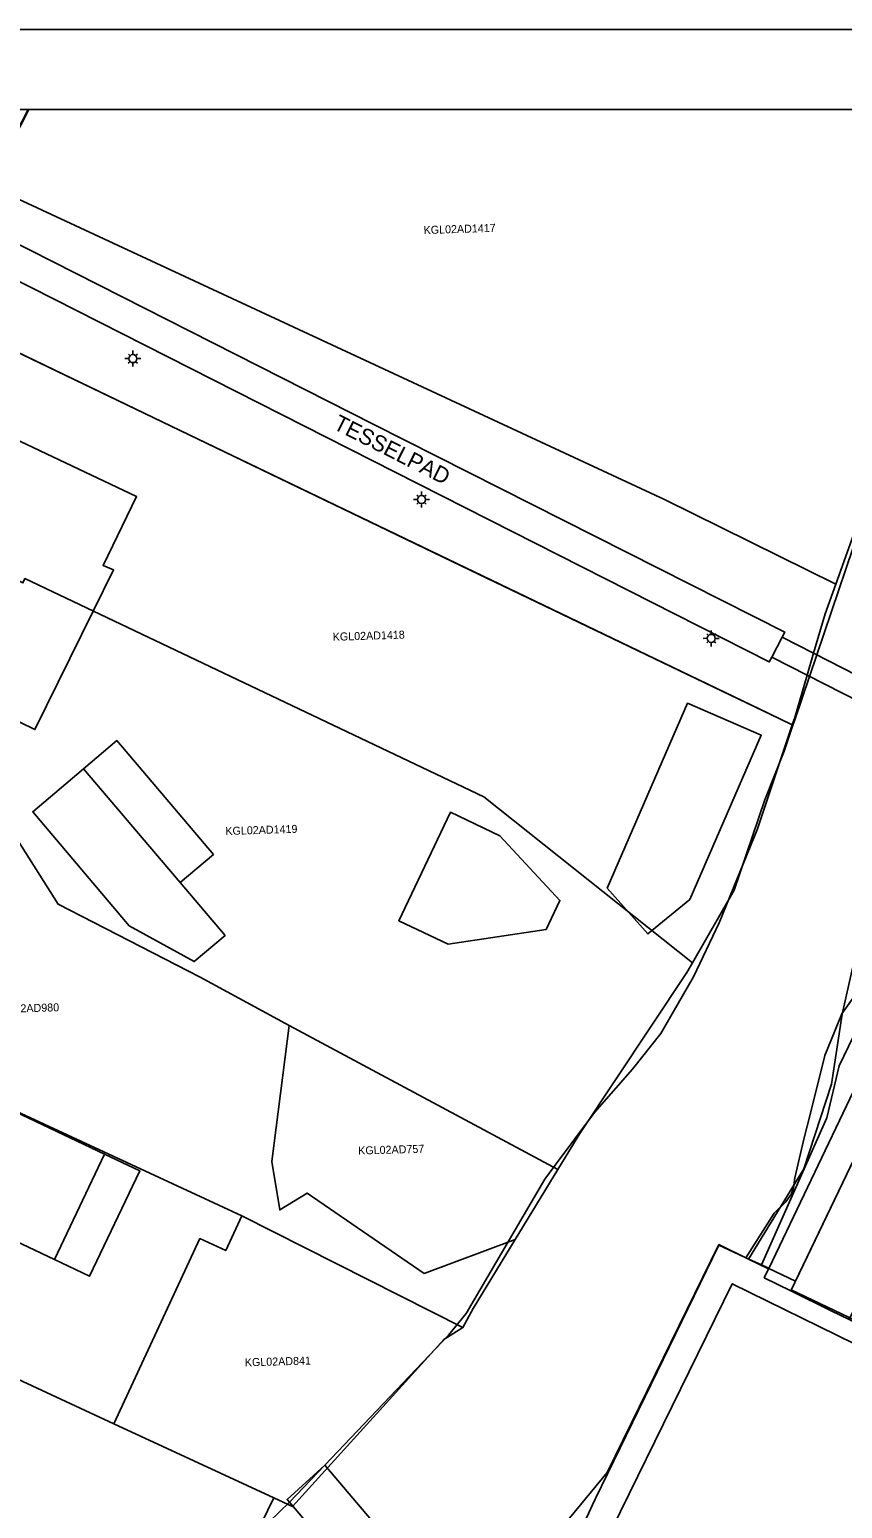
# Model space of a CAD drawing. Extents: x 124901 to 125496, y 515369 to 515789.
# Drawn here: x 125170.8 to 125221.6, y 515696.7 to 515789 of the extents above; entities that cross this region are included whole.
import ezdxf

# ---------------------------------------------------------------- set-up
doc = ezdxf.new("R2010")
doc.units = 0
for name, color, linetype in [('Alg Kaders', 7, 'Continuous'), ('Brug', 7, 'Continuous'), ('Gebouw', 7, 'Continuous'), ('Lichtmast', 7, 'Continuous'), ('Luifel', 7, 'Continuous'), ('Onbegroeid terrein', 7, 'Continuous'), ('Perceelnummers', 7, 'Continuous'), ('Perceelsgrenzen', 7, 'Continuous'), ('Scheiding', 7, 'Continuous'), ('Teksten', 7, 'Continuous'), ('Vegetatie', 7, 'Continuous'), ('Voetpad', 7, 'Continuous'), ('Water', 7, 'Continuous')]:
    doc.layers.add(name, color=color, linetype=linetype)

msp = doc.modelspace()

# ---------------------------------------------------------------- linework, layer by layer
at = {"layer": 'Alg Kaders'}
for points in [[(125495.925, 515789.043), (124901.425, 515789.043), (124901.425, 515368.543), (125495.925, 515368.543)], [(125490.925, 515784.043), (124906.425, 515784.043), (124906.425, 515373.543), (125490.925, 515373.543)]]:
    msp.add_lwpolyline(points, close=True, dxfattribs=at)
at = {"layer": 'Brug'}
for points in [[(125219.366, 515748.715), (125229.281, 515743.647), (125232.287, 515742.11), (125232.917, 515743.354), (125230.576, 515744.551), (125219.765, 515750.077), (125217.796, 515751.084), (125217.158, 515749.844)], [(125189.261, 515699.364), (125186.899, 515697.22), (125187.039, 515697.055), (125195.202, 515687.42), (125196.287, 515686.14), (125196.996, 515685.303), (125197.091, 515685.385), (125199.401, 515687.39), (125198.282, 515688.711), (125197.646, 515689.462)]]:
    msp.add_lwpolyline(points, close=True, dxfattribs=at)
at = {"layer": 'Gebouw'}
for points in [[(125175.405, 515755.565), (125177.505, 515759.864), (125162.592, 515766.936), (125159.137, 515759.843), (125155.723, 515752.834), (125171.151, 515745.315), (125174.794, 515752.716), (125176.062, 515755.292)], [(125209.421, 515732.552), (125212.04, 515734.701), (125216.496, 515744.954), (125211.896, 515746.954), (125206.881, 515735.415)], [(125171.024, 515740.177), (125177.045, 515733.06), (125181.094, 515730.815), (125183.026, 515732.454), (125180.223, 515735.757), (125174.192, 515742.865)], [(125203.927, 515734.646), (125200.188, 515738.677), (125197.104, 515740.146), (125193.874, 515733.367), (125196.958, 515731.898), (125203.063, 515732.832)], [(125174.566, 515711.161), (125177.695, 515717.757), (125175.507, 515718.795), (125172.378, 515712.199)], [(125255.78, 515690.51), (125245.235, 515695.69), (125214.684, 515710.698), (125206.118, 515693.205), (125212.846, 515689.903), (125213.638, 515689.515), (125213.117, 515688.464), (125240.37, 515675.06), (125252.16, 515640.32), (125262.108, 515643.719), (125262.17, 515643.74), (125258.434, 515654.722), (125250.16, 515679.04)]]:
    msp.add_lwpolyline(points, close=True, dxfattribs=at)
msp.add_lwpolyline([(125153.374, 515714.021), (125153.846, 515715.015), (125157.55, 515713.258), (125157.764, 515713.709), (125158.848, 515713.195), (125160.949, 515717.622), (125172.378, 515712.199), (125175.507, 515718.795), (125166.472, 515723.081), (125164.972, 515719.919), (125150.824, 515726.632), (125149.752, 515724.373), (125148.397, 515725.016), (125145.525, 515718.963), (125149.328, 515717.158), (125148.857, 515716.164)], dxfattribs=at)
at = {"layer": 'Lichtmast'}
for p, q in [((125177.27, 515768.785), (125177.27, 515768.985)), ((125176.97, 515768.486), (125176.77, 515768.485)), ((125177.058, 515768.273), (125176.986, 515768.202)), ((125177.058, 515768.697), (125176.988, 515768.768)), ((125177.27, 515768.185), (125177.27, 515767.985)), ((125177.482, 515768.697), (125177.553, 515768.769)), ((125177.482, 515768.273), (125177.552, 515768.202)), ((125177.57, 515768.485), (125177.77, 515768.485)), ((125194.989, 515759.682), (125194.789, 515759.681)), ((125195.077, 515759.893), (125195.007, 515759.964)), ((125195.289, 515759.981), (125195.289, 515760.181)), ((125195.501, 515759.893), (125195.572, 515759.965)), ((125195.589, 515759.681), (125195.789, 515759.681)), ((125195.077, 515759.469), (125195.005, 515759.398)), ((125195.289, 515759.381), (125195.289, 515759.181)), ((125195.501, 515759.469), (125195.571, 515759.398)), ((125213.163, 515751.225), (125213.093, 515751.296)), ((125213.375, 515751.313), (125213.375, 515751.513)), ((125213.587, 515751.225), (125213.658, 515751.297)), ((125213.075, 515751.014), (125212.875, 515751.013)), ((125213.163, 515750.801), (125213.091, 515750.73)), ((125213.375, 515750.713), (125213.375, 515750.513)), ((125213.587, 515750.801), (125213.657, 515750.73)), ((125213.675, 515751.013), (125213.875, 515751.013))]:
    msp.add_line(p, q, dxfattribs=at)
for centre in [(125177.27, 515768.485), (125195.289, 515759.681), (125213.375, 515751.013)]:
    msp.add_circle(centre, 0.25, dxfattribs=at)
at = {"layer": 'Luifel'}
msp.add_lwpolyline([(125174.192, 515742.865), (125180.223, 515735.757), (125182.295, 515737.515), (125176.264, 515744.623)], close=True, dxfattribs=at)
at = {"layer": 'Onbegroeid terrein'}
for points in [[(125185.766, 515695.807), (125187.039, 515697.055), (125189.261, 515699.364), (125196.973, 515707.476), (125198.082, 515708.838), (125202.98, 515717.233), (125203.636, 515718.109), (125206.093, 515721.388), (125208.465, 515724.107), (125210.228, 515726.326), (125212.278, 515729.857), (125213.861, 515733.245), (125216.273, 515739.114), (125218.436, 515745.604), (125217.7, 515745.958), (125198.292, 515755.3), (125179.658, 515764.268), (125172.005, 515767.951), (125164.373, 515771.625)], [(125275.477, 515693.742), (125260.628, 515701.114), (125267.475, 515715.233), (125267.782, 515716.109), (125267.836, 515716.841), (125267.71, 515717.476), (125267.54, 515718.12), (125267.198, 515718.856), (125266.405, 515719.871), (125265.455, 515720.581), (125241.464, 515732.301), (125231.203, 515737.071), (125218.626, 515710.857), (125218.367, 515710.317), (125225.087, 515707.115), (125230.506, 515704.533), (125235.595, 515702.107), (125236.826, 515704.531), (125239.632, 515703.106), (125238.438, 515700.753), (125245.988, 515697.155), (125245.235, 515695.69)], [(125148.857, 515716.164), (125149.328, 515717.158), (125145.525, 515718.963), (125148.397, 515725.016), (125149.752, 515724.373), (125150.824, 515726.632), (125164.972, 515719.919), (125166.472, 515723.081), (125175.507, 515718.795), (125177.695, 515717.757), (125174.566, 515711.161), (125172.378, 515712.199), (125160.949, 515717.622), (125158.848, 515713.195), (125157.764, 515713.709), (125157.55, 515713.258), (125153.846, 515715.015), (125153.374, 515714.021)]]:
    msp.add_lwpolyline(points, dxfattribs=at)
for points in [[(125177.505, 515759.864), (125175.405, 515755.565), (125176.062, 515755.292), (125174.794, 515752.716), (125171.151, 515745.315), (125155.723, 515752.834), (125159.137, 515759.843), (125162.592, 515766.936)], [(125219.366, 515748.715), (125219.765, 515750.077), (125217.796, 515751.084), (125217.158, 515749.844)], [(125212.04, 515734.701), (125209.421, 515732.552), (125206.881, 515735.415), (125211.896, 515746.954), (125216.496, 515744.954)], [(125177.045, 515733.06), (125171.024, 515740.177), (125174.192, 515742.865), (125180.223, 515735.757), (125183.026, 515732.454), (125181.094, 515730.815)], [(125200.188, 515738.677), (125203.927, 515734.646), (125203.063, 515732.832), (125196.958, 515731.898), (125193.874, 515733.367), (125197.104, 515740.146)]]:
    msp.add_lwpolyline(points, close=True, dxfattribs=at)
at = {"layer": 'Perceelsgrenzen'}
for points in [[(125224.894, 515784.043), (125230.41, 515780.94), (125229.187, 515776.22), (125228.706, 515774.74), (125224.518, 515763.453), (125218.587, 515745.917), (125218.475, 515745.585), (125216.926, 515746.331), (125179.658, 515764.268), (125164.351, 515771.635), (125164.824, 515772.601), (125170.723, 515784.043)], [(125178.006, 515680.755), (125186.062, 515697.321), (125187.24, 515696.774), (125196.709, 515707.236), (125196.839, 515707.316), (125197.874, 515707.953), (125198.52, 515709.14), (125201.139, 515713.453), (125203.792, 515717.823), (125205.167, 515720.086), (125211.845, 515730.131), (125212.2, 515730.749), (125214.804, 515735.288), (125216.718, 515740.932), (125217.928, 515743.967), (125218.475, 515745.585), (125218.587, 515745.917), (125224.518, 515763.453), (125228.706, 515774.74), (125229.187, 515776.22), (125230.41, 515780.94), (125230.43, 515781.016), (125231.172, 515784.043)], [(125246.348, 515784.043), (125245.734, 515782.581), (125244.244, 515779.306), (125242.228, 515774.739), (125238.993, 515767.861), (125237.156, 515763.177), (125234.495, 515756.117), (125232.252, 515751.115), (125230.368, 515746.673), (125228.984, 515742.963), (125227.864, 515740.192), (125225.843, 515736.5), (125222.198, 515730.407), (125221.542, 515727.531), (125220.881, 515723.169), (125219.159, 515717.869), (125215.704, 515712.24), (125213.855, 515713.14), (125206.879, 515698.908), (125203.838, 515695.207)], [(125222.198, 515730.407), (125221.542, 515727.531), (125220.881, 515723.169), (125219.159, 515717.869), (125215.704, 515712.24), (125216.956, 515711.631), (125216.681, 515711.069), (125218.337, 515710.255), (125231.203, 515737.071)], [(125203.838, 515695.207), (125206.879, 515698.908), (125213.855, 515713.14), (125215.704, 515712.24), (125216.956, 515711.631), (125216.681, 515711.069), (125218.337, 515710.255), (125220.87, 515709.01), (125221.983, 515708.463), (125231.055, 515704.004), (125239.133, 515700.033), (125246.913, 515696.209)]]:
    msp.add_lwpolyline(points, dxfattribs=at)
for points in [[(125158.19, 515760.294), (125161.532, 515767.441), (125162.165, 515767.173), (125164.351, 515771.635), (125179.658, 515764.268), (125216.926, 515746.331), (125218.475, 515745.585), (125217.928, 515743.967), (125216.718, 515740.932), (125214.804, 515735.288), (125212.2, 515730.749), (125199.189, 515741.106), (125174.81, 515752.708), (125170.532, 515754.746), (125170.403, 515754.476)], [(125187.033, 515726.823), (125181.47, 515729.84), (125172.61, 515734.4), (125168.766, 515740.47), (125153.027, 515747.884), (125154.775, 515751.601), (125154.24, 515751.848), (125158.19, 515760.294), (125170.403, 515754.476), (125170.532, 515754.746), (125174.81, 515752.708), (125199.189, 515741.106), (125212.2, 515730.749), (125211.845, 515730.131), (125205.167, 515720.086), (125203.792, 515717.823)], [(125187.033, 515726.823), (125185.954, 515718.332), (125186.437, 515715.305), (125188.155, 515716.36), (125195.464, 515711.337), (125201.139, 515713.453), (125198.52, 515709.14), (125197.874, 515707.953), (125184.068, 515714.928), (125166.821, 515722.932), (125167.043, 515723.435), (125166.317, 515723.701), (125157.502, 515727.638), (125146.929, 515732.544), (125146.469, 515732.779), (125146.026, 515732.974), (125149.651, 515740.707), (125153.027, 515747.884), (125168.766, 515740.47), (125172.61, 515734.4), (125181.47, 515729.84)], [(125234.873, 515735.365), (125221.983, 515708.463), (125220.87, 515709.01), (125218.337, 515710.255), (125231.203, 515737.071)], [(125142.898, 515725.078), (125146.469, 515732.779), (125146.929, 515732.544), (125157.502, 515727.638), (125166.317, 515723.701), (125167.043, 515723.435), (125166.821, 515722.932), (125184.068, 515714.928), (125183.065, 515712.767), (125181.45, 515713.516), (125176.083, 515701.951), (125158.392, 515710.161), (125156.223, 515710.107), (125155.15, 515710.599), (125139.906, 515718.982)], [(125201.139, 515713.453), (125195.464, 515711.337), (125188.155, 515716.36), (125186.437, 515715.305), (125185.954, 515718.332), (125187.033, 515726.823), (125203.792, 515717.823)], [(125137.276, 515713.452), (125137.985, 515715.068), (125139.344, 515717.837), (125155.15, 515710.599), (125156.223, 515710.107), (125158.392, 515710.161), (125176.083, 515701.951), (125186.062, 515697.321), (125178.006, 515680.755), (125177.522, 515679.612), (125176.942, 515679.918), (125158.693, 515689.231), (125159.008, 515689.848), (125151.696, 515693.579), (125139.631, 515699.806), (125132.057, 515703.978)], [(125196.709, 515707.236), (125187.24, 515696.774), (125186.062, 515697.321), (125176.083, 515701.951), (125181.45, 515713.516), (125183.065, 515712.767), (125184.068, 515714.928), (125197.874, 515707.953), (125196.839, 515707.316)]]:
    msp.add_lwpolyline(points, close=True, dxfattribs=at)
at = {"layer": 'Scheiding'}
for points in [[(125189.261, 515699.364), (125196.973, 515707.476), (125198.082, 515708.838), (125202.98, 515717.233)], [(125206.161, 515697.277), (125213.86, 515713.103), (125215.095, 515712.527)], [(125216.505, 515711.87), (125216.872, 515711.699)], [(125205.966, 515696.876), (125206.161, 515697.277)]]:
    msp.add_lwpolyline(points, dxfattribs=at)
at = {"layer": 'Vegetatie'}
msp.add_lwpolyline([(125170.766, 515784.043), (125168.314, 515779.28), (125210.455, 515759.695), (125221.146, 515754.39), (125222.56, 515758.362), (125224.934, 515765.294), (125227.567, 515772.077), (125229.817, 515777.954), (125230.73, 515780.863), (125225.038, 515784.043)], dxfattribs=at)
for points in [[(125168.314, 515779.28), (125166.739, 515776.22), (125167.454, 515775.842), (125167.919, 515776.738), (125192.32, 515764.374), (125217.962, 515751.406), (125217.796, 515751.084), (125219.765, 515750.077), (125220.486, 515752.536), (125221.146, 515754.39), (125210.455, 515759.695)], [(125179.658, 515764.268), (125198.292, 515755.3), (125217.7, 515745.958), (125218.436, 515745.604), (125218.588, 515746.061), (125219.366, 515748.715), (125217.158, 515749.844), (125217, 515749.536), (125193.636, 515761.396), (125168.064, 515774.363), (125167.717, 515773.674), (125165.906, 515774.602), (125164.373, 515771.625), (125172.005, 515767.951)], [(125236.794, 515739.52), (125232.144, 515741.828), (125231.86, 515741.274), (125228.811, 515739.413), (125225.487, 515732.838), (125221.367, 515724.3), (125220.596, 515721.056), (125216.505, 515711.87), (125216.872, 515711.699), (125216.982, 515711.641), (125230.182, 515739.338), (125235.465, 515736.802)]]:
    msp.add_lwpolyline(points, close=True, dxfattribs=at)
at = {"layer": 'Voetpad'}
for points in [[(125217.796, 515751.084), (125217.962, 515751.406), (125192.32, 515764.374), (125167.919, 515776.738), (125167.454, 515775.842), (125166.739, 515776.22), (125165.906, 515774.602), (125167.717, 515773.674), (125168.064, 515774.363), (125193.636, 515761.396), (125217, 515749.536), (125217.158, 515749.844)], [(125219.366, 515748.715), (125229.281, 515743.647), (125232.287, 515742.11), (125232.917, 515743.354), (125230.576, 515744.551), (125219.765, 515750.077), (125217.796, 515751.084), (125217.158, 515749.844)], [(125196.996, 515685.303), (125197.091, 515685.385), (125199.401, 515687.39), (125198.282, 515688.711), (125197.646, 515689.462), (125189.261, 515699.364), (125186.899, 515697.22), (125187.039, 515697.055), (125195.202, 515687.42), (125196.287, 515686.14)]]:
    msp.add_lwpolyline(points, close=True, dxfattribs=at)
for points in [[(125230.182, 515739.338), (125216.982, 515711.641), (125218.626, 515710.857), (125231.203, 515737.071)], [(125216.982, 515711.641), (125216.872, 515711.699), (125216.505, 515711.87), (125215.535, 515712.322), (125215.095, 515712.527), (125213.86, 515713.103), (125206.161, 515697.277), (125205.966, 515696.876), (125205.734, 515696.388), (125203.843, 515692.413), (125205.399, 515691.807), (125201.897, 515684.742), (125202.169, 515684.435), (125203.02, 515684.016), (125206.246, 515682.438), (125208.05, 515681.565), (125208.083, 515681.549)], [(125245.942, 515641.911), (125248.221, 515635.188), (125253.325, 515636.886), (125253.239, 515637.141), (125252.16, 515640.32), (125240.37, 515675.06), (125213.117, 515688.464), (125213.638, 515689.515), (125212.846, 515689.903), (125206.118, 515693.205), (125214.684, 515710.698), (125245.235, 515695.69), (125245.988, 515697.155), (125238.438, 515700.753), (125235.595, 515702.107), (125230.506, 515704.533), (125225.087, 515707.115), (125218.367, 515710.317), (125218.626, 515710.857), (125216.982, 515711.641)]]:
    msp.add_lwpolyline(points, dxfattribs=at)
at = {"layer": 'Water'}
for points in [[(125222.56, 515758.362), (125221.146, 515754.39), (125220.486, 515752.536), (125219.765, 515750.077), (125219.366, 515748.715), (125218.588, 515746.061), (125218.436, 515745.604), (125216.273, 515739.114), (125213.861, 515733.245), (125212.278, 515729.857), (125210.228, 515726.326), (125208.465, 515724.107), (125206.093, 515721.388), (125203.636, 515718.109), (125202.98, 515717.233), (125198.082, 515708.838), (125196.973, 515707.476), (125189.261, 515699.364), (125187.039, 515697.055), (125185.766, 515695.807)], [(125222.988, 515729.621), (125221.527, 515727.556), (125220.46, 515724.959), (125219.579, 515721.341), (125219.161, 515719.718), (125218.593, 515717.317), (125218.512, 515716.691), (125218.385, 515716.308), (125218.025, 515715.821), (125217.295, 515715.102), (125215.535, 515712.322), (125216.505, 515711.87), (125220.596, 515721.056), (125221.367, 515724.3), (125225.487, 515732.838)], [(125205.734, 515696.388), (125205.966, 515696.876), (125206.161, 515697.277), (125213.86, 515713.103), (125215.095, 515712.527), (125215.535, 515712.322), (125217.295, 515715.102), (125218.025, 515715.821), (125218.385, 515716.308), (125218.512, 515716.691), (125218.593, 515717.317), (125219.161, 515719.718), (125219.579, 515721.341), (125220.46, 515724.959), (125221.527, 515727.556), (125222.988, 515729.621)]]:
    msp.add_lwpolyline(points, dxfattribs=at)

# ---------------------------------------------------------------- texts
at = {"layer": 'Perceelnummers'}
for s, rotation, p in [('KGL02AD1417', 1.83034, (125195.429, 515776.267)), ('KGL02AD1418', 1.83027, (125189.754, 515750.857)), ('KGL02AD1419', 1.83019, (125183.053, 515738.723)), ('KGL02AD980', 1.63183, (125168.547, 515727.6)), ('KGL02AD757', 1.6321, (125191.342, 515718.761)), ('KGL02AD841', 1.63202, (125184.266, 515705.532))]:
    msp.add_text(s, height=0.5, rotation=rotation, dxfattribs=at).set_placement(p)
at = {"layer": 'Teksten'}
msp.add_text('TESSELPAD', height=1, rotation=333.2, dxfattribs=at).set_placement((125189.713, 515764.13))

doc.saveas('drawing.dxf')
